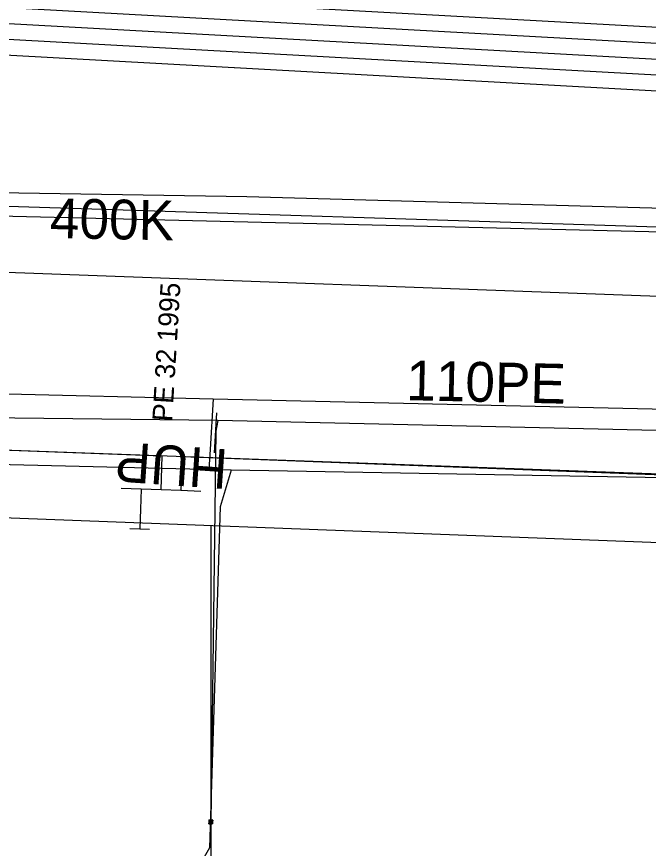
# Model space of a CAD drawing. Extents: x -746464 to -745690, y -1051581 to -1049993.
# Drawn here: x -746117.42 to -746101.53, y -1051042.46 to -1051021.54 of the extents above; entities that cross this region are included whole.
import ezdxf

# ---------------------------------------------------------------- set-up
doc = ezdxf.new("R2010")
doc.units = 0
for name, color, linetype in [('04_CETIN_NN', 7, 'Continuous'), ('04_CETIN_sdelovaci_podzem', 7, 'Continuous'), ('37_TVNET_sdelovaci_televizni kabely', 7, 'Continuous'), ('45_Eltodo_sdelovaci_kabel_ovladaci', 7, 'Continuous'), ('45_Eltodo_vedeni_NN_zemni', 7, 'Continuous'), ('48_Prazs_plynarenska_STL', 7, 'Continuous'), ('48_Prazs_plynarenska_STL_popisy', 7, 'Continuous'), ('51_PVaK_kanal_jednotna_overena poloha_rad', 7, 'Continuous'), ('51_PVaK_kanal_popisy', 7, 'Continuous'), ('51_PVaK_vodovod_chranicky_objekty', 7, 'Continuous'), ('51_PVaK_vodovod_overena poloha_pripojka', 7, 'Continuous'), ('51_PVaK_vodovod_overena poloha_rad', 7, 'Continuous'), ('51_PVaK_vodovod_popisy', 7, 'Continuous'), ('55_PREdi_NN', 7, 'Continuous'), ('55_PREdi_NN_pripojovaci_misto', 7, 'Continuous')]:
    doc.layers.add(name, color=color, linetype=linetype)

msp = doc.modelspace()

# ---------------------------------------------------------------- linework, layer by layer
at = {"layer": '04_CETIN_NN'}
msp.add_lwpolyline([(-746057.75, -1051028.08), (-746087.26, -1051027.3), (-746131.43, -1051026.23), (-746132.58, -1051026.03), (-746137.16, -1051023.83), (-746146.04, -1051015.8), (-746146.14, -1051015.34)], dxfattribs=at)
at = {"layer": '04_CETIN_sdelovaci_podzem'}
for points in [[(-746057.75, -1051028.08), (-746087.26, -1051027.3), (-746131.43, -1051026.23), (-746132.58, -1051026.03), (-746137.16, -1051023.83), (-746146.04, -1051015.8), (-746146.14, -1051015.34)], [(-746051.11, -1051027.62), (-746084.98, -1051026.78), (-746095.15, -1051026.53), (-746111.63, -1051026.07), (-746132.51, -1051025.74)], [(-746112.02, -1051032.95), (-746139.83, -1051032.28)], [(-746112.02, -1051032.95), (-746112.3, -1051033.87), (-746112.57, -1051042.45), (-746113.31, -1051043.75), (-746113.28, -1051046.99), (-746113.71, -1051049.63)], [(-746094.98, -1051033.25), (-746112.02, -1051032.95)], [(-746112.3, -1051033.87), (-746112.57, -1051042.45)]]:
    msp.add_lwpolyline(points, dxfattribs=at)
at = {"layer": '37_TVNET_sdelovaci_televizni kabely'}
for points in [[(-745984.595, -1050626.363), (-746079.15, -1050602.616), (-746117.902, -1050728.62), (-746140.499, -1050964.785), (-746150.343, -1051014.385), (-746134.374, -1051025.766), (-746053.56, -1051028.358)], [(-746164.092, -1051025.501), (-746164.092, -1051032.378), (-746094.407, -1051035.026)], [(-746112.537, -1051034.337), (-746112.537, -1051052.816), (-746116.943, -1051052.816)]]:
    msp.add_lwpolyline(points, dxfattribs=at)
at = {"layer": '45_Eltodo_sdelovaci_kabel_ovladaci'}
for points in [[(-746165.45, -1051019.12), (-746164.645, -1051018.484), (-746163.012, -1051015.524), (-746155.55, -1051020.103), (-746128.916, -1051021.082), (-746094.892, -1051022.957), (-746062.41, -1051024.051), (-746028.782, -1051025.923), (-745993.864, -1051027.813), (-745962.878, -1051029.504), (-745938.694, -1051029.59), (-745937.853, -1051017.666)], [(-746165.45, -1051019.12), (-746164.312, -1051018.623), (-746162.86, -1051016.086), (-746155.668, -1051020.501), (-746128.943, -1051021.481), (-746094.909, -1051023.356), (-746062.428, -1051024.45), (-746028.804, -1051026.323), (-745993.885, -1051028.213), (-745962.902, -1051029.904), (-745931.905, -1051029.989), (-745932.65, -1051042.244), (-745896.705, -1051050.601), (-745888.091, -1051054.568), (-745887.715, -1051053.926), (-745888.006, -1051054.643), (-745887.529, -1051054.877), (-745867.231, -1051055.559), (-745868.29, -1051094.52)]]:
    msp.add_lwpolyline(points, dxfattribs=at)
at = {"layer": '45_Eltodo_vedeni_NN_zemni'}
for points in [[(-746165.45, -1051019.12), (-746165.385, -1051018.211), (-746163.315, -1051014.399), (-746155.315, -1051019.309), (-746128.86, -1051020.284), (-746094.856, -1051022.157), (-746062.375, -1051023.251), (-746028.738, -1051025.124), (-745993.82, -1051027.014), (-745962.83, -1051028.706), (-745954.147, -1051028.453), (-745931.268, -1051028.32), (-745933.203, -1051055.903)], [(-746165.45, -1051019.12), (-746164.568, -1051017.613), (-746163.161, -1051014.992), (-746155.446, -1051019.718), (-746128.935, -1051020.682), (-746094.904, -1051022.556), (-746062.441, -1051023.642), (-746028.749, -1051025.516), (-745993.88, -1051027.407), (-745962.99, -1051029.049), (-745953.059, -1051029.043), (-745952.784, -1051028.189)], [(-746128.971, -1051021.88), (-746094.927, -1051023.756)]]:
    msp.add_lwpolyline(points, dxfattribs=at)
at = {"layer": '48_Prazs_plynarenska_STL'}
for points in [[(-746142.85, -1051030.58), (-746140.03, -1051030.48), (-746112.47, -1051031.15), (-746095.18, -1051031.55), (-746077.47, -1051032.14), (-746054.623, -1051033.192)], [(-746112.47, -1051031.15), (-746112.548, -1051032.43)], [(-746112.548, -1051032.43), (-746112.579, -1051032.929)]]:
    msp.add_lwpolyline(points, dxfattribs=at)
at = {"layer": '51_PVaK_kanal_jednotna_overena poloha_rad'}
msp.add_line((-746135.666, -1051027.315), (-746099.3, -1051028.64), dxfattribs=at)
at = {"layer": '51_PVaK_vodovod_chranicky_objekty'}
for p, q in [((-746112.441, -1051032.51), (-746112.384, -1051031.51)), ((-746112.582, -1051041.848), (-746112.48, -1051041.75)), ((-746112.58, -1051041.748), (-746112.581, -1051041.768)), ((-746112.482, -1051041.85), (-746112.58, -1051041.748)), ((-746112.58, -1051041.748), (-746112.56, -1051041.749)), ((-746112.48, -1051041.75), (-746112.5, -1051041.749)), ((-746112.48, -1051041.75), (-746112.481, -1051041.77)), ((-746112.582, -1051041.848), (-746112.581, -1051041.828)), ((-746112.582, -1051041.848), (-746112.562, -1051041.849)), ((-746112.482, -1051041.85), (-746112.502, -1051041.849)), ((-746112.482, -1051041.85), (-746112.481, -1051041.83))]:
    msp.add_line(p, q, dxfattribs=at)
msp.add_lwpolyline([(-746112.53, -1051041.749), (-746112.535, -1051041.749), (-746112.54, -1051041.75), (-746112.545, -1051041.751), (-746112.55, -1051041.753), (-746112.555, -1051041.756), (-746112.559, -1051041.759), (-746112.564, -1051041.762), (-746112.568, -1051041.766), (-746112.571, -1051041.77), (-746112.574, -1051041.773), (-746112.577, -1051041.778), (-746112.579, -1051041.783), (-746112.58, -1051041.788), (-746112.581, -1051041.793), (-746112.581, -1051041.798), (-746112.581, -1051041.803), (-746112.58, -1051041.808), (-746112.579, -1051041.813), (-746112.577, -1051041.818), (-746112.574, -1051041.823), (-746112.571, -1051041.827), (-746112.568, -1051041.832), (-746112.564, -1051041.836), (-746112.56, -1051041.839), (-746112.557, -1051041.842), (-746112.552, -1051041.845), (-746112.547, -1051041.847), (-746112.542, -1051041.848), (-746112.537, -1051041.849), (-746112.532, -1051041.849), (-746112.527, -1051041.849), (-746112.522, -1051041.848), (-746112.517, -1051041.847), (-746112.512, -1051041.845), (-746112.507, -1051041.842), (-746112.502, -1051041.839), (-746112.498, -1051041.836), (-746112.494, -1051041.832), (-746112.491, -1051041.828), (-746112.488, -1051041.825), (-746112.485, -1051041.82), (-746112.483, -1051041.815), (-746112.482, -1051041.81), (-746112.481, -1051041.805), (-746112.481, -1051041.8), (-746112.481, -1051041.795), (-746112.482, -1051041.79), (-746112.483, -1051041.785), (-746112.485, -1051041.78), (-746112.488, -1051041.775), (-746112.491, -1051041.77), (-746112.494, -1051041.766), (-746112.498, -1051041.762), (-746112.502, -1051041.759), (-746112.505, -1051041.756), (-746112.51, -1051041.753), (-746112.515, -1051041.751), (-746112.52, -1051041.75), (-746112.525, -1051041.749), (-746112.53, -1051041.749)], dxfattribs=at)
at = {"layer": '51_PVaK_vodovod_overena poloha_pripojka'}
msp.add_line((-746112.36, -1051031.7), (-746112.41, -1051031.97), dxfattribs=at)
msp.add_lwpolyline([(-746112.41, -1051031.97), (-746112.442, -1051034.627), (-746112.53, -1051041.8)], dxfattribs=at)
at = {"layer": '51_PVaK_vodovod_overena poloha_rad'}
msp.add_lwpolyline([(-746077.51, -1051033.22), (-746095.07, -1051032.09), (-746112.36, -1051031.7), (-746140.08, -1051031.38), (-746159.77, -1051029.67)], dxfattribs=at)
at = {"layer": '55_PREdi_NN'}
for points in [[(-745933.351, -1051040.912), (-745941.504, -1051040.452), (-745958.538, -1051039.744), (-745969.12, -1051039.482), (-746015.2, -1051036.705), (-746033.432, -1051035.653), (-746045.186, -1051035.092), (-746119.381, -1051032.383), (-746168.04, -1051032.305), (-746181.2, -1051031.6)], [(-746113.786, -1051033.446), (-746113.755, -1051032.598), (-746119.381, -1051032.383), (-746140.748, -1051032.473), (-746140.745, -1051033.3)], [(-746096.799, -1051033.982), (-746096.772, -1051033.244), (-746113.255, -1051032.616), (-746113.286, -1051033.464)], [(-746112.786, -1051033.482), (-746113.286, -1051033.464), (-746113.786, -1051033.446), (-746114.286, -1051033.428), (-746114.785, -1051033.409)], [(-746114.286, -1051033.428), (-746114.304, -1051033.927)]]:
    msp.add_lwpolyline(points, dxfattribs=at)
at = {"layer": '55_PREdi_NN_pripojovaci_misto'}
for p, q in [((-746114.304, -1051033.927), (-746114.321, -1051034.427)), ((-746114.571, -1051034.418), (-746114.072, -1051034.435))]:
    msp.add_line(p, q, dxfattribs=at)

# ---------------------------------------------------------------- texts
at = {"layer": '48_Prazs_plynarenska_STL_popisy'}
for s, height, rotation, p in [('PE 32 1995', 0.5, 86.5129, (-746113.507, -1051031.732)), ('HUP', 1, 176, (-746112.079, -1051032.429))]:
    msp.add_text(s, height=height, rotation=rotation, dxfattribs=at).set_placement(p)
at = {"layer": '51_PVaK_kanal_popisy'}
msp.add_text('400K', height=1, rotation=358.9133, dxfattribs=at).set_placement((-746116.589, -1051027.108))
at = {"layer": '51_PVaK_vodovod_popisy'}
msp.add_text('110PE', height=1, rotation=358.7086, dxfattribs=at).set_placement((-746107.627, -1051031.186))

doc.saveas('drawing.dxf')
